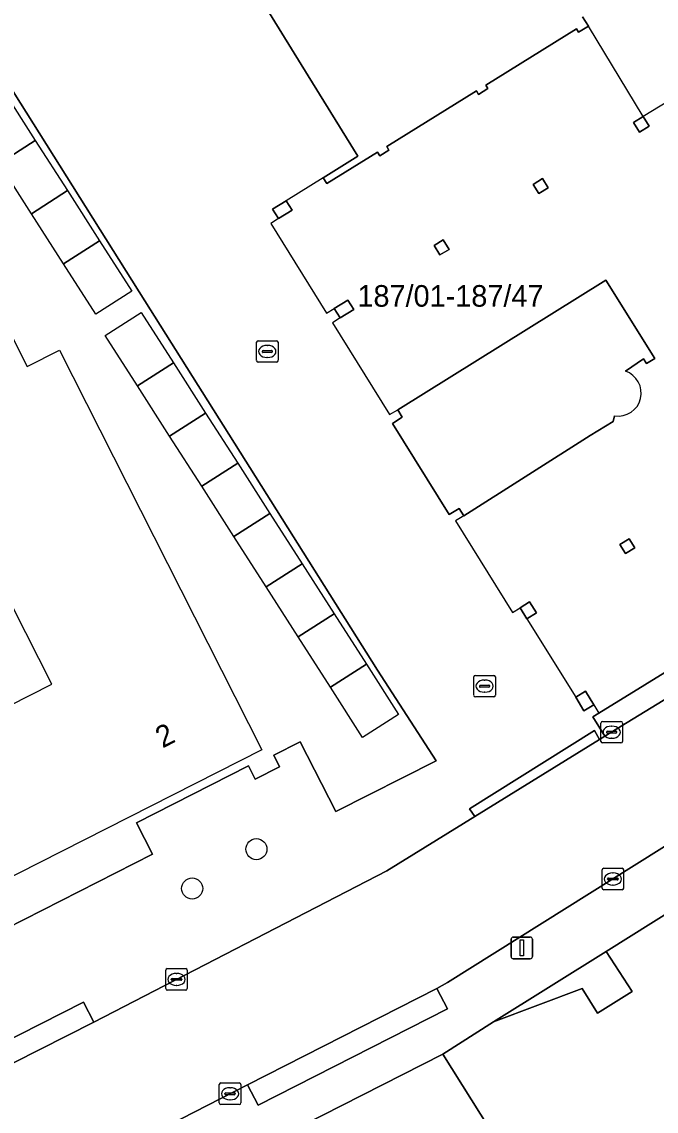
# Model space of a CAD drawing. Extents: x 159888 to 160761, y 384031 to 384750.
# Drawn here: x 160569.1 to 160598.5, y 384304.2 to 384354.7 of the extents above; entities that cross this region are included whole.
import ezdxf

# ---------------------------------------------------------------- set-up
doc = ezdxf.new("R2010")
doc.units = 0
for name, color, linetype in [('IMGEO_Boom', 7, 'Continuous'), ('IMGEO_Erf', 7, 'Continuous'), ('IMGEO_Kolk', 7, 'Continuous'), ('IMGEO_Lichtmast', 7, 'Continuous'), ('IMGEO_Pand', 7, 'Continuous'), ('IMGEO_Pand_nummerreeks', 7, 'Continuous'), ('IMGEO_Pand_overbouw', 7, 'Continuous'), ('IMGEO_Pand_vergunning_verleend', 7, 'Continuous'), ('IMGEO_Rijbaan_lokaal_open', 7, 'Continuous'), ('IMGEO_Voetpad_open', 7, 'Continuous')]:
    doc.layers.add(name, color=color, linetype=linetype)

msp = doc.modelspace()

# ---------------------------------------------------------------- linework, layer by layer
at = {"layer": 'IMGEO_Boom'}
for centre in [(160579.986, 384316.341), (160577.009, 384314.518)]:
    msp.add_circle(centre, 0.489, dxfattribs=at)
at = {"layer": 'IMGEO_Erf'}
for points in [[(160595.104, 384354.934), (160595.373, 384354.493), (160594.923, 384354.214), (160594.823, 384354.376), (160590.618, 384351.765), (160590.718, 384351.603), (160590.285, 384351.334), (160590.185, 384351.496), (160586.03, 384348.916), (160586.13, 384348.754), (160585.705, 384348.491), (160585.605, 384348.653), (160583.243, 384347.199), (160583.074, 384347.47), (160584.687, 384348.472), (160582.063, 384352.728), (160571.03, 384370.619)], [(160566.993, 384306.736), (160571.974, 384309.253), (160572.443, 384308.324), (160586.028, 384315.337), (160590.108, 384317.85), (160589.869, 384318.218), (160595.657, 384321.842), (160595.889, 384321.422), (160596.143, 384321.577), (160595.584, 384322.484), (160595.862, 384322.654), (160600.124, 384325.268), (160600.464, 384325.477), (160604.727, 384328.091), (160609.747, 384331.17), (160611.084, 384335.6), (160609.425, 384338.231), (160606.794, 384342.482), (160606.584, 384342.823), (160603.953, 384347.074), (160603.742, 384347.414), (160601.085, 384351.65), (160600.365, 384352.829), (160597.222, 384357.971)], [(160568.09, 384352.422), (160574.55, 384342.177), (160585.604, 384324.648), (160588.311, 384320.443), (160583.665, 384318.082), (160582.016, 384321.325), (160580.788, 384320.701), (160581.061, 384320.164), (160579.931, 384319.59), (160579.619, 384320.206), (160574.426, 384317.567), (160575.166, 384316.112), (160564.1, 384310.488)], [(160596.591, 384336.427), (160596.526, 384336.172), (160595.459, 384335.516), (160589.596, 384331.799), (160589.385, 384332.139), (160588.927, 384331.854), (160586.291, 384336.085), (160586.749, 384336.37), (160586.537, 384336.709), (160596.188, 384342.719)], [(160596.188, 384342.719), (160598.448, 384339.09), (160598.066, 384338.852), (160597.928, 384339.073), (160597.09, 384338.505)], [(160644.978, 384250), (160614.619, 384298.372), (160618.52, 384300.827), (160616.202, 384304.508), (160597.498, 384292.735), (160592.849, 384300.122), (160591.287, 384302.603), (160588.624, 384306.834), (160582.096, 384303.521), (160584.318, 384299.185), (160585.688, 384296.513), (160585.901, 384296.096), (160586.721, 384296.518), (160588.13, 384293.779), (160582.195, 384290.726), (160580.786, 384293.465), (160575.718, 384290.858), (160570.633, 384288.242), (160565.536, 384285.62)]]:
    msp.add_lwpolyline(points, dxfattribs=at)
for points in [[(160597.466, 384350.03), (160597.918, 384350.308), (160598.197, 384349.857), (160597.745, 384349.579)], [(160592.818, 384347.165), (160593.252, 384347.433), (160593.515, 384347.008), (160593.081, 384346.74)], [(160581.366, 384346.408), (160581.641, 384345.967), (160581.012, 384345.576), (160580.737, 384346.017)], [(160588.221, 384344.332), (160588.647, 384344.594), (160588.92, 384344.152), (160588.494, 384343.89)], [(160584.225, 384341.802), (160584.5, 384341.361), (160583.871, 384340.97), (160583.596, 384341.411)], [(160596.834, 384330.471), (160597.259, 384330.733), (160597.521, 384330.309), (160597.096, 384330.047)], [(160592.207, 384327.537), (160592.649, 384327.812), (160592.965, 384327.303), (160592.523, 384327.028)], [(160594.787, 384323.383), (160595.238, 384323.662), (160595.621, 384323.041), (160595.17, 384322.762)]]:
    msp.add_lwpolyline(points, close=True, dxfattribs=at)
msp.add_arc((160596.751, 384337.487), 1.072, 261.4108, 71.5832, dxfattribs=at)
at = {"layer": 'IMGEO_Kolk'}
for p, q in [((160580.065, 384339.917), (160580.917, 384339.917)), ((160579.99, 384338.991), (160579.99, 384339.843)), ((160580.249, 384339.411), (160580.249, 384339.423)), ((160580.292, 384339.46), (160580.69, 384339.46)), ((160580.478, 384339.697), (160580.503, 384339.697)), ((160580.733, 384339.423), (160580.733, 384339.411)), ((160580.991, 384339.843), (160580.991, 384338.991)), ((160580.917, 384338.917), (160580.065, 384338.917)), ((160580.687, 384339.374), (160580.289, 384339.374)), ((160580.501, 384339.137), (160580.476, 384339.137)), ((160590.062, 384323.475), (160590.062, 384324.327)), ((160590.137, 384324.401), (160590.989, 384324.401)), ((160591.063, 384324.327), (160591.063, 384323.475)), ((160590.321, 384323.895), (160590.321, 384323.907)), ((160590.759, 384323.858), (160590.361, 384323.858)), ((160590.364, 384323.944), (160590.762, 384323.944)), ((160590.55, 384324.181), (160590.575, 384324.181)), ((160590.805, 384323.907), (160590.805, 384323.895)), ((160590.989, 384323.401), (160590.137, 384323.401)), ((160590.573, 384323.621), (160590.548, 384323.621)), ((160596.028, 384322.266), (160596.88, 384322.266)), ((160595.953, 384321.34), (160595.953, 384322.192)), ((160596.212, 384321.76), (160596.212, 384321.772)), ((160596.65, 384321.723), (160596.252, 384321.723)), ((160596.255, 384321.809), (160596.653, 384321.809)), ((160596.441, 384322.046), (160596.466, 384322.046)), ((160596.696, 384321.772), (160596.696, 384321.76)), ((160596.954, 384322.192), (160596.954, 384321.34)), ((160596.88, 384321.266), (160596.028, 384321.266)), ((160596.464, 384321.486), (160596.439, 384321.486)), ((160596.008, 384314.534), (160596.008, 384315.386)), ((160596.083, 384315.46), (160596.935, 384315.46)), ((160596.496, 384315.24), (160596.521, 384315.24)), ((160597.009, 384315.386), (160597.009, 384314.534)), ((160596.267, 384314.954), (160596.267, 384314.966)), ((160596.705, 384314.917), (160596.307, 384314.917)), ((160596.31, 384315.003), (160596.708, 384315.003)), ((160596.519, 384314.68), (160596.494, 384314.68)), ((160596.751, 384314.966), (160596.751, 384314.954)), ((160596.935, 384314.46), (160596.083, 384314.46)), ((160575.781, 384309.879), (160575.781, 384310.731)), ((160575.856, 384310.805), (160576.708, 384310.805)), ((160576.782, 384310.731), (160576.782, 384309.879)), ((160576.04, 384310.299), (160576.04, 384310.311)), ((160576.478, 384310.262), (160576.08, 384310.262)), ((160576.083, 384310.348), (160576.481, 384310.348)), ((160576.269, 384310.585), (160576.294, 384310.585)), ((160576.524, 384310.311), (160576.524, 384310.299)), ((160576.708, 384309.805), (160575.856, 384309.805)), ((160576.292, 384310.025), (160576.267, 384310.025)), ((160578.264, 384304.576), (160578.264, 384305.428)), ((160578.339, 384305.502), (160579.191, 384305.502)), ((160578.752, 384305.282), (160578.777, 384305.282)), ((160579.265, 384305.428), (160579.265, 384304.576)), ((160578.523, 384304.996), (160578.523, 384305.008)), ((160578.961, 384304.959), (160578.563, 384304.959)), ((160578.566, 384305.045), (160578.964, 384305.045)), ((160578.775, 384304.722), (160578.75, 384304.722)), ((160579.007, 384305.008), (160579.007, 384304.996)), ((160579.191, 384304.502), (160578.339, 384304.502))]:
    msp.add_line(p, q, dxfattribs=at)
for points in [[(160580.065, 384339.917), (160580.917, 384339.917)], [(160579.99, 384338.991), (160579.99, 384339.843)], [(160580.991, 384339.843), (160580.991, 384338.991)], [(160580.917, 384338.917), (160580.065, 384338.917)], [(160590.062, 384323.475), (160590.062, 384324.327)], [(160590.137, 384324.401), (160590.989, 384324.401)], [(160591.063, 384324.327), (160591.063, 384323.475)], [(160590.989, 384323.401), (160590.137, 384323.401)], [(160596.028, 384322.266), (160596.88, 384322.266)], [(160595.953, 384321.34), (160595.953, 384322.192)], [(160596.954, 384322.192), (160596.954, 384321.34)], [(160596.88, 384321.266), (160596.028, 384321.266)], [(160596.008, 384314.534), (160596.008, 384315.386)], [(160596.083, 384315.46), (160596.935, 384315.46)], [(160597.009, 384315.386), (160597.009, 384314.534)], [(160596.935, 384314.46), (160596.083, 384314.46)], [(160575.781, 384309.879), (160575.781, 384310.731)], [(160575.856, 384310.805), (160576.708, 384310.805)], [(160576.782, 384310.731), (160576.782, 384309.879)], [(160576.708, 384309.805), (160575.856, 384309.805)], [(160578.264, 384304.576), (160578.264, 384305.428)], [(160578.339, 384305.502), (160579.191, 384305.502)], [(160579.265, 384305.428), (160579.265, 384304.576)], [(160579.191, 384304.502), (160578.339, 384304.502)]]:
    msp.add_lwpolyline(points, dxfattribs=at)
for centre, radius, start, end in [((160580.067, 384339.841), 0.0765, 91.552, 178.448), ((160580.067, 384339.841), 0.0765, 91.552, 178.448), ((160580.915, 384339.841), 0.0765, 1.552, 88.448), ((160580.915, 384339.841), 0.0765, 1.552, 88.448), ((160580.289, 384339.42), 0.0403, 85.8775, 175.7526), ((160580.286, 384339.41), 0.0366, 178.938, 274.7102), ((160580.69, 384339.417), 0.043, 264.8664, 352.4533), ((160580.694, 384339.422), 0.0386, 1.7309, 96.639), ((160580.067, 384338.993), 0.0765, 181.552, 268.448), ((160580.067, 384338.993), 0.0765, 181.552, 268.448), ((160580.915, 384338.993), 0.0765, 271.552, 358.448), ((160580.915, 384338.993), 0.0765, 271.552, 358.448), ((160590.139, 384324.325), 0.0765, 91.552, 178.448), ((160590.139, 384324.325), 0.0765, 91.552, 178.448), ((160590.987, 384324.325), 0.0765, 1.552, 88.448), ((160590.987, 384324.325), 0.0765, 1.552, 88.448), ((160590.361, 384323.904), 0.0403, 85.8775, 175.7526), ((160590.358, 384323.894), 0.0366, 178.938, 274.7102), ((160590.762, 384323.901), 0.043, 264.8664, 352.4533), ((160590.766, 384323.906), 0.0386, 1.7309, 96.639), ((160590.139, 384323.477), 0.0765, 181.552, 268.448), ((160590.139, 384323.477), 0.0765, 181.552, 268.448), ((160590.987, 384323.477), 0.0765, 271.552, 358.448), ((160590.987, 384323.477), 0.0765, 271.552, 358.448), ((160596.03, 384322.19), 0.0765, 91.552, 178.448), ((160596.03, 384322.19), 0.0765, 91.552, 178.448), ((160596.878, 384322.19), 0.0765, 1.552, 88.448), ((160596.878, 384322.19), 0.0765, 1.552, 88.448), ((160596.252, 384321.769), 0.0403, 85.8775, 175.7526), ((160596.249, 384321.759), 0.0366, 178.938, 274.7102), ((160596.653, 384321.766), 0.043, 264.8664, 352.4533), ((160596.657, 384321.771), 0.0386, 1.7309, 96.639), ((160596.03, 384321.342), 0.0765, 181.552, 268.448), ((160596.03, 384321.342), 0.0765, 181.552, 268.448), ((160596.878, 384321.342), 0.0765, 271.552, 358.448), ((160596.878, 384321.342), 0.0765, 271.552, 358.448), ((160596.085, 384315.384), 0.0765, 91.552, 178.448), ((160596.085, 384315.384), 0.0765, 91.552, 178.448), ((160596.933, 384315.384), 0.0765, 1.552, 88.448), ((160596.933, 384315.384), 0.0765, 1.552, 88.448), ((160596.307, 384314.963), 0.0403, 85.8775, 175.7526), ((160596.304, 384314.953), 0.0366, 178.938, 274.7102), ((160596.708, 384314.96), 0.043, 264.8664, 352.4533), ((160596.712, 384314.965), 0.0386, 1.7309, 96.639), ((160596.085, 384314.536), 0.0765, 181.552, 268.448), ((160596.085, 384314.536), 0.0765, 181.552, 268.448), ((160596.933, 384314.536), 0.0765, 271.552, 358.448), ((160596.933, 384314.536), 0.0765, 271.552, 358.448), ((160575.858, 384310.729), 0.0765, 91.552, 178.448), ((160575.858, 384310.729), 0.0765, 91.552, 178.448), ((160576.706, 384310.729), 0.0765, 1.552, 88.448), ((160576.706, 384310.729), 0.0765, 1.552, 88.448), ((160576.08, 384310.308), 0.0403, 85.8775, 175.7526), ((160576.077, 384310.298), 0.0366, 178.938, 274.7102), ((160576.481, 384310.305), 0.043, 264.8664, 352.4533), ((160576.485, 384310.31), 0.0386, 1.7309, 96.639), ((160575.858, 384309.881), 0.0765, 181.552, 268.448), ((160575.858, 384309.881), 0.0765, 181.552, 268.448), ((160576.706, 384309.881), 0.0765, 271.552, 358.448), ((160576.706, 384309.881), 0.0765, 271.552, 358.448), ((160578.341, 384305.426), 0.0765, 91.552, 178.448), ((160578.341, 384305.426), 0.0765, 91.552, 178.448), ((160579.189, 384305.426), 0.0765, 1.552, 88.448), ((160579.189, 384305.426), 0.0765, 1.552, 88.448), ((160578.341, 384304.578), 0.0765, 181.552, 268.448), ((160578.341, 384304.578), 0.0765, 181.552, 268.448), ((160578.563, 384305.005), 0.0403, 85.8775, 175.7526), ((160578.56, 384304.995), 0.0366, 178.938, 274.7102), ((160578.964, 384305.002), 0.043, 264.8664, 352.4533), ((160578.968, 384305.007), 0.0386, 1.7309, 96.639), ((160579.189, 384304.578), 0.0765, 271.552, 358.448), ((160579.189, 384304.578), 0.0765, 271.552, 358.448)]:
    msp.add_arc(centre, radius, start, end, dxfattribs=at)
for centre, major_axis, ratio, start_param, end_param in [((160580.477, 384339.417), (-0.387, 0.002), 0.722429, 4.712389, 7.853982), ((160580.502, 384339.417), (-0.39, 0.002), 0.717154, 1.570796, 4.712389), ((160590.549, 384323.901), (-0.387, 0.002), 0.722429, 4.712389, 7.853982), ((160590.574, 384323.901), (-0.39, 0.002), 0.717154, 1.570796, 4.712389), ((160596.44, 384321.766), (-0.387, 0.002), 0.722429, 4.712389, 7.853982), ((160596.465, 384321.766), (-0.39, 0.002), 0.717154, 1.570796, 4.712389), ((160596.495, 384314.96), (-0.387, 0.002), 0.722429, 4.712389, 7.853982), ((160596.52, 384314.96), (-0.39, 0.002), 0.717154, 1.570796, 4.712389), ((160576.268, 384310.305), (-0.387, 0.002), 0.722429, 4.712389, 7.853982), ((160576.293, 384310.305), (-0.39, 0.002), 0.717154, 1.570796, 4.712389), ((160578.751, 384305.002), (-0.387, 0.002), 0.722429, 4.712389, 7.853982), ((160578.776, 384305.002), (-0.39, 0.002), 0.717154, 1.570796, 4.712389)]:
    msp.add_ellipse(centre, major_axis=major_axis, ratio=ratio, start_param=start_param, end_param=end_param, dxfattribs=at)
at = {"layer": 'IMGEO_Lichtmast'}
for p, q in [((160591.791, 384311.366), (160591.791, 384312.166)), ((160591.791, 384312.166), (160591.791, 384311.366)), ((160591.891, 384312.266), (160592.681, 384312.266)), ((160592.681, 384312.266), (160591.891, 384312.266)), ((160592.781, 384312.166), (160592.781, 384311.366)), ((160592.781, 384311.366), (160592.781, 384312.166)), ((160592.681, 384311.266), (160591.891, 384311.266)), ((160591.891, 384311.266), (160592.681, 384311.266))]:
    msp.add_line(p, q, dxfattribs=at)
msp.add_lwpolyline([(160592.211, 384312.141), (160592.361, 384312.141), (160592.361, 384311.391), (160592.211, 384311.391), (160592.211, 384312.141)], dxfattribs=at)
for centre, start, end in [((160591.891, 384312.166), 90, 180), ((160591.891, 384312.166), 90, 180), ((160592.681, 384312.166), 0, 90), ((160592.681, 384312.166), 360, 90), ((160591.891, 384311.366), 180, 270), ((160591.891, 384311.366), 180, 270), ((160592.681, 384311.366), 270, 0), ((160592.681, 384311.366), 270, 0)]:
    msp.add_arc(centre, 0.1, start, end, dxfattribs=at)
at = {"layer": 'IMGEO_Pand'}
for points in [[(160571.03, 384370.619), (160582.063, 384352.728), (160584.687, 384348.472), (160583.074, 384347.47), (160583.243, 384347.199), (160585.605, 384348.653), (160585.705, 384348.491), (160586.13, 384348.754), (160586.03, 384348.916), (160590.185, 384351.496), (160590.285, 384351.334), (160590.718, 384351.603), (160590.618, 384351.765), (160594.823, 384354.376), (160594.923, 384354.214), (160595.373, 384354.493), (160595.104, 384354.934)], [(160597.09, 384338.505), (160597.928, 384339.073), (160598.066, 384338.852), (160598.448, 384339.09), (160596.188, 384342.719), (160586.537, 384336.709), (160586.749, 384336.37), (160586.291, 384336.085), (160588.927, 384331.854), (160589.385, 384332.139), (160589.596, 384331.799), (160595.459, 384335.516), (160596.526, 384336.172), (160596.591, 384336.427)]]:
    msp.add_lwpolyline(points, dxfattribs=at)
for points in [[(160548.767, 384340.417), (160548.858, 384340.463), (160553.091, 384332.138), (160555.55, 384327.303), (160558.407, 384321.685), (160564.1, 384310.488), (160575.166, 384316.112), (160574.426, 384317.567), (160579.619, 384320.206), (160579.931, 384319.59), (160581.061, 384320.164), (160580.788, 384320.701), (160582.016, 384321.325), (160583.665, 384318.082), (160588.311, 384320.443), (160585.604, 384324.648), (160574.55, 384342.177), (160568.09, 384352.422), (160548.143, 384341.701)], [(160597.918, 384350.308), (160597.466, 384350.03), (160597.745, 384349.579), (160598.197, 384349.857)], [(160593.081, 384346.74), (160593.515, 384347.008), (160593.252, 384347.433), (160592.818, 384347.165)], [(160581.366, 384346.408), (160580.737, 384346.017), (160581.012, 384345.576), (160581.641, 384345.967)], [(160588.494, 384343.89), (160588.92, 384344.152), (160588.647, 384344.594), (160588.221, 384344.332)], [(160583.596, 384341.411), (160583.871, 384340.97), (160584.5, 384341.361), (160584.225, 384341.802)], [(160597.096, 384330.047), (160597.521, 384330.309), (160597.259, 384330.733), (160596.834, 384330.471)], [(160592.207, 384327.537), (160592.523, 384327.028), (160592.965, 384327.303), (160592.649, 384327.812)], [(160594.787, 384323.383), (160595.17, 384322.762), (160595.621, 384323.041), (160595.238, 384323.662)], [(160616.202, 384304.508), (160620.618, 384307.289), (160612.108, 384320.804), (160610.863, 384320.807), (160608.91, 384319.592), (160605.748, 384316.587), (160606.486, 384315.46), (160604.914, 384314.428), (160603.685, 384316.3), (160596.202, 384311.606), (160597.402, 384309.739), (160595.802, 384308.735), (160595.092, 384309.885), (160590.982, 384308.334), (160588.624, 384306.834), (160591.287, 384302.603), (160592.849, 384300.122), (160597.498, 384292.735)]]:
    msp.add_lwpolyline(points, close=True, dxfattribs=at)
msp.add_arc((160596.751, 384337.487), 1.072, 261.4108, 71.5832, dxfattribs=at)
at = {"layer": 'IMGEO_Pand_overbouw'}
for points in [[(160595.373, 384354.493), (160594.923, 384354.214), (160594.823, 384354.376), (160590.618, 384351.765), (160590.718, 384351.603), (160590.285, 384351.334), (160590.185, 384351.496), (160586.03, 384348.916), (160586.13, 384348.754), (160585.705, 384348.491), (160585.605, 384348.653), (160583.243, 384347.199), (160583.074, 384347.47), (160581.366, 384346.408), (160581.641, 384345.967), (160581.012, 384345.576), (160580.656, 384345.355), (160583.24, 384341.19), (160583.596, 384341.411), (160584.225, 384341.802), (160584.5, 384341.361), (160583.871, 384340.97), (160583.515, 384340.749), (160586.151, 384336.501), (160586.537, 384336.709), (160596.188, 384342.719), (160598.448, 384339.09), (160598.066, 384338.852), (160597.928, 384339.073), (160597.09, 384338.505)], [(160599.842, 384351.492), (160597.918, 384350.308), (160595.373, 384354.493)], [(160596.591, 384336.427), (160596.526, 384336.172), (160595.459, 384335.516), (160589.596, 384331.799), (160589.214, 384331.565), (160591.851, 384327.316), (160592.207, 384327.537), (160592.649, 384327.812), (160592.965, 384327.303), (160592.523, 384327.028), (160594.787, 384323.383), (160595.238, 384323.662), (160595.621, 384323.041), (160595.862, 384322.654), (160600.124, 384325.268)]]:
    msp.add_lwpolyline(points, dxfattribs=at)
msp.add_lwpolyline([(160590.982, 384308.334), (160595.092, 384309.885), (160595.802, 384308.735), (160597.402, 384309.739), (160596.202, 384311.606)], close=True, dxfattribs=at)
msp.add_arc((160596.751, 384337.487), 1.072, 261.4108, 71.5832, dxfattribs=at)
at = {"layer": 'IMGEO_Pand_vergunning_verleend'}
for points in [[(160541.273, 384332.177), (160556.824, 384340.057), (160552.227, 384349.128), (160561.67, 384353.913), (160569.365, 384338.725), (160570.851, 384339.478), (160580.24, 384320.948), (160564.785, 384313.117), (160561.568, 384319.466), (160570.497, 384323.991), (160564.463, 384335.899), (160551.281, 384329.219), (160561.805, 384308.451), (160555.684, 384305.35), (160551.316, 384313.97), (160550.665, 384313.64)], [(160566.576, 384350.464), (160568.246, 384351.533), (160569.737, 384349.204), (160568.067, 384348.135)], [(160568.067, 384348.135), (160569.737, 384349.204), (160571.228, 384346.876), (160569.558, 384345.806)], [(160569.558, 384345.806), (160571.228, 384346.876), (160572.719, 384344.547), (160571.049, 384343.478)], [(160571.049, 384343.478), (160572.719, 384344.547), (160574.21, 384342.219), (160572.54, 384341.149)], [(160572.976, 384340.152), (160574.646, 384341.221), (160576.137, 384338.893), (160574.467, 384337.824)], [(160574.467, 384337.824), (160576.137, 384338.893), (160577.628, 384336.564), (160575.958, 384335.495)], [(160575.958, 384335.495), (160577.628, 384336.564), (160579.119, 384334.236), (160577.449, 384333.167)], [(160577.449, 384333.167), (160579.119, 384334.236), (160580.61, 384331.907), (160578.94, 384330.838)], [(160578.94, 384330.838), (160580.61, 384331.907), (160582.1, 384329.579), (160580.431, 384328.51)], [(160580.431, 384328.51), (160582.1, 384329.579), (160583.591, 384327.25), (160581.922, 384326.181)], [(160581.922, 384326.181), (160583.591, 384327.25), (160585.082, 384324.922), (160583.413, 384323.853)], [(160583.413, 384323.853), (160585.082, 384324.922), (160586.573, 384322.593), (160584.904, 384321.524)]]:
    msp.add_lwpolyline(points, close=True, dxfattribs=at)
at = {"layer": 'IMGEO_Rijbaan_lokaal_open'}
for points in [[(160612.124, 384331.359), (160596.143, 384321.577), (160595.889, 384321.422), (160590.108, 384317.85), (160586.028, 384315.337), (160572.443, 384308.324), (160567.462, 384305.807), (160566.53, 384305.339), (160555.538, 384299.708), (160550.478, 384297.137), (160546.731, 384295.217), (160546.235, 384294.964), (160538.022, 384290.775), (160536.409, 384289.932), (160530.529, 384286.928), (160530.447, 384286.864), (160533.164, 384281.656), (160533.808, 384281.997), (160534.575, 384282.359), (160579.578, 384305.42), (160588.356, 384309.89)], [(160588.356, 384309.89), (160588.848, 384310.16), (160607.558, 384321.885), (160615.782, 384325.978), (160616.128, 384326.145)]]:
    msp.add_lwpolyline(points, dxfattribs=at)
at = {"layer": 'IMGEO_Voetpad_open'}
for points in [[(160611.084, 384335.6), (160609.747, 384331.17), (160604.727, 384328.091), (160600.464, 384325.477), (160600.124, 384325.268), (160595.862, 384322.654), (160595.584, 384322.484), (160596.143, 384321.577), (160612.124, 384331.359)], [(160595.889, 384321.422), (160595.657, 384321.842), (160589.869, 384318.218), (160590.108, 384317.85)], [(160590.982, 384308.334), (160595.092, 384309.885), (160595.802, 384308.735), (160597.402, 384309.739), (160596.202, 384311.606)], [(160588.356, 384309.89), (160579.578, 384305.42), (160580.064, 384304.467), (160588.842, 384308.937)], [(160571.974, 384309.253), (160566.993, 384306.736), (160567.462, 384305.807), (160572.443, 384308.324)]]:
    msp.add_lwpolyline(points, close=True, dxfattribs=at)
for points in [[(160582.038, 384303.635), (160582.096, 384303.521), (160588.624, 384306.834), (160590.982, 384308.334), (160596.202, 384311.606), (160603.685, 384316.3), (160608.91, 384319.592), (160610.863, 384320.807), (160612.108, 384320.804), (160620.206, 384320.788), (160616.807, 384326.31)], [(160616.128, 384326.145), (160615.782, 384325.978), (160607.558, 384321.885), (160588.848, 384310.16), (160588.356, 384309.89), (160588.842, 384308.937), (160580.064, 384304.467), (160579.578, 384305.42), (160534.575, 384282.359), (160533.808, 384281.997), (160533.164, 384281.656), (160532.184, 384281.146)]]:
    msp.add_lwpolyline(points, dxfattribs=at)

# ---------------------------------------------------------------- texts
at = {"layer": 'IMGEO_Pand_nummerreeks'}
msp.add_text('187/01-187/47', height=1, dxfattribs=at).set_placement((160584.668, 384341.494))
msp.add_text('2', height=1, rotation=26.939, dxfattribs=at).set_placement((160575.634, 384321.008))

doc.saveas('drawing.dxf')
